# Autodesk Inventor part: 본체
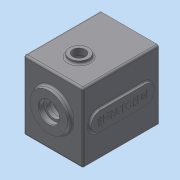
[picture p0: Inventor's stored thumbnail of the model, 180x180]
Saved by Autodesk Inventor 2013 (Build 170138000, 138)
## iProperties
Created: 2016-02
Part Number: 본체
Material: 알루미늄 6061
Document SubType Name: Modeling
Designer: mduedu
Density: 2.71 g/cm^3
Mass: 1515.92 g
Surface Area: 1077.08 cm^2
Volume: 559.38 cm^3
Author: mduedu
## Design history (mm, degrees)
sketch "스케치1"
  geometry: L1 (-47, -47)-(47, -47); L2 (47, -47)-(47, 63); L3 (47, 63)-(-47, 63); L4 (-47, 63)-(-47, -47); 2 further points
  constraints: 8 end point, 2 parallel, 1 horizontal, 1 midpoint, 1 perpendicular, 1 vertical alignment
  dimensions: "d0" = 94 distance of L2.end L3.end; "d155" = 110 distance of L1.end L2.end; "d156" = 47 distance from line of L1 point (0, 0)
extrude "돌출1" new body sketch "스케치1" distance "d2" = 120; taper "d3" = 0 deg
sketch "스케치3"
  geometry: L1 (47, -47)-(-47, -47) reference; L2 (47, 63)-(47, -47) reference; L3 (-47, 63)-(47, 63) reference; L4 (-47, -47)-(-47, 63) reference; L5 (37, 53)-(37, -37); L6 (37, -37)-(-37, -37); L7 (-37, -37)-(-37, 53); L8 (-37, 53)-(37, 53); 1 further point
  constraints: 8 end point, 3 other
  dimensions: "d226" = 10 distance between parallel lines of L8 L3
extrude "돌출3" cut sketch "스케치3" distance "d11" = 110; taper "d12" = 0 deg
sketch "스케치4"
  geometry: C1 r 21 at (0, 11); 1 further point
  constraints: 1 centre point, 1 vertical alignment
  dimensions: "d13" = 21 radius of C1; "d227" = 11 distance of point (0, 0) C1.centre
extrude "돌출4" join sketch "스케치4" distance "d16" = 7; taper "d17" = 0 deg
sketch "스케치5"
  geometry: C1 r 15 at (0, -20); 1 further point
  constraints: 1 centre point, 1 vertical alignment
  dimensions: "d18" = 15 radius of C1; "d20" = 20 distance of point (0, 0) C1.centre
extrude "돌출5" join sketch "스케치5" distance "d21" = 7; taper "d22" = 0 deg
sketch "스케치6"
  geometry: C1 r 30 at (0, 11); A1 r 21 centre (0, 11) between (8.978, -7.984) and (-8.978, -7.984) reference; 1 further point
  constraints: 1 centre point, 1 coincident
  dimensions: "d228" = 60 diameter of C1
extrude "돌출6" join sketch "스케치6" distance "d25" = 7; taper "d26" = -3 deg
hole "구멍1" diameter "d29" = 35; stored, may be unused: countersink angle "d33" = 90 deg, drill point angle "d35" = 0 deg; dims "d27" = 10, "d28" = 10, "d30" = 6, "d31" = 4, "d32" = 2, "d34" = 10
hole "구멍2" diameter "d38" = 22; stored, may be unused: countersink angle "d42" = 90 deg, drill point angle "d44" = 0 deg; dims "d36" = 10, "d37" = 10, "d39" = 6, "d40" = 4, "d41" = 2, "d43" = 7
hole "구멍3" diameter "d47" = 19; stored, may be unused: countersink angle "d51" = 90 deg, drill point angle "d53" = 0 deg; dims "d45" = 10, "d46" = 10, "d48" = 6, "d49" = 4, "d50" = 2, "d52" = 1
hole "구멍4" diameter "d56" = 32; stored, may be unused: countersink angle "d60" = 90 deg, drill point angle "d62" = 0 deg; dims "d57" = 6, "d58" = 4, "d59" = 2, "d61" = 8, "d220" = 10, "d221" = 10
hole "구멍5" diameter "d65" = 25; stored, may be unused: countersink angle "d69" = 90 deg, drill point angle "d71" = 0 deg; dims "d63" = 10, "d64" = 10, "d66" = 6, "d67" = 4, "d68" = 2, "d70" = 8
fillet "모깎기2" dims "d73" = 0.3
fillet "모깎기3" dims "d74" = 2
chamfer "모따기1" distance "d75" = 1; stored, may be unused: second distance "d76" = 2, angle "d77" = 45 deg
fillet "모깎기4" dims "d78" = 3
fillet "모깎기23" dims "d240" = 1
fillet "모깎기20" dims "d229" = 3
sketch "스케치23"
  geometry: L1 (-37, 53)-(37, 53) reference; L2 (37, 53)-(37, -37) reference; L3 (37, -37)-(-37, -37) reference; L4 (-37, -37)-(-37, 53) reference; L5 (44, -47)-(-44, -47) reference; L6 (47, 60)-(47, -44) reference; L7 (-44, 63)-(44, 63) reference; L8 (-47, -44)-(-47, 60) reference; C1 r 10 at (-37, 53); C2 r 10 at (37, 53); C3 r 10 at (-37, -37); C4 r 10 at (37, -37); A1 r 3 centre (-44, -44) between (-47, -44) and (-44, -47) reference; A2 r 3 centre (44, -44) between (44, -47) and (47, -44) reference; A3 r 3 centre (44, 60) between (47, 60) and (44, 63) reference; A4 r 3 centre (-44, 60) between (-44, 63) and (-47, 60) reference; 1 further point
  constraints: 4 centre point, 4 coincident, 3 equal radius
  dimensions: "d230" = 20 diameter of C1
extrude "돌출22" join sketch "스케치23" stored distance "d235" = 10; taper "d236" = 0 deg
fillet "모깎기21" dims "d237" = 3
node "작업 평면1"
fillet "모깎기22" dims "d239" = 1
sketch "스케치12"
  geometry: A1 r 10 centre (-37, 53) between (-34.692, 43.27) and (-27.27, 50.692) reference; A2 r 10 centre (37, 53) between (27.27, 50.692) and (34.692, 43.27) reference; A3 r 10 centre (37, -37) between (34.692, -27.27) and (27.27, -34.692) reference; A4 r 10 centre (-37, -37) between (-27.27, -34.692) and (-34.692, -27.27) reference; 5 further points
  constraints: 4 coincident
hole "구멍6" sketch "스케치12" at (-37, 53), (37, 53), (37, -37), (-37, -37) diameter "d122" = 3.242; stored, may be unused: countersink angle "d126" = 90 deg, drill point angle "d128" = 120 deg; dims "d123" = 7, "d124" = 4, "d125" = 2, "d127" = 9
sketch "스케치20"
  geometry: L1 (44, 0)-(-44, 0) reference; L2 (44, -120)-(-44, -120) reference; L3 (0, 0)-(0, -120); L4 (-44, -120)-(-44, 0) reference; L5 (44, 0)-(44, -120) reference; C1 r 10 at (0, -79)
  constraints: 2 end point, 1 centre point, 1 midpoint, 1 point on line
  dimensions: "d189" = 20 diameter of C1; "d190" = 41 distance from line of C1.centre L2
extrude "돌출19" cut sketch "스케치20" stored distance "d191" = 10; taper "d192" = 0 deg
sketch "스케치18"
  geometry: C1 r 15 at (0, -79); C2 r 10 at (0, -79) reference; 1 further point
  constraints: 1 centre point, 1 concentric
  dimensions: "d174" = 30 diameter of C1
extrude "돌출17" join sketch "스케치18" distance "d175" = 5; taper "d176" = 0 deg
fillet "모깎기16" dims "d177" = 3
sketch "스케치19"
  geometry: C1 r 15 at (24.351, 79); C2 r 10 at (24.351, 79) reference; 1 further point
  constraints: 1 centre point, 1 concentric
  dimensions: "d178" = 30 diameter of C1
extrude "돌출18" cut sketch "스케치19" distance "d181" = 5; taper "d182" = 0 deg
chamfer "모따기5" distance "d183" = 1; stored, may be unused: second distance "d184" = 2, angle "d185" = 45 deg
fillet "모깎기24" dims "d242" = 3, "d243" = 3
sketch "스케치24"
  geometry: L1 (-95, 67)-(-25, 67); L2 (-25, 67)-(-25, 37); L3 (-25, 37)-(-95, 37); L4 (-95, 37)-(-95, 67); L5 (0, 0)-(0, 104) reference; L6 (-95, 52)-(-25, 52); L7 (-60, 67)-(-60, 37); A1 r 15 centre (-95, 52) between (-95, 37) and (-95, 67); A2 r 15 centre (-25, 52) between (-25, 67) and (-25, 37); A3 r 15 centre (-25, 52) between (-25, 37) and (-25, 67); A4 r 15 centre (-95, 52) between (-95, 67) and (-95, 37); 2 further points
  constraints: 12 end point, 8 point on circle, 5 midpoint, 4 centre point, 2 parallel, 2 perpendicular, 1 horizontal, 1 horizontal alignment
  dimensions: "d244" = 60 distance between parallel lines of L7 L5; "d245" = 100 dimension on A2 A1; "d246" = 30 distance between parallel lines of L3 L1
extrude "돌출23" join sketch "스케치24" distance "d247" = 3; taper "d248" = 0 deg
fillet "모깎기25" dims "d249" = 3
sketch "스케치25"
  geometry: L1 (-25, 67)-(-95, 67) reference; L2 (-95, 37)-(-25, 37) reference; A1 r 15 centre (-95, 52) between (-95, 67) and (-95, 37) reference; A2 r 15 centre (-25, 52) between (-25, 37) and (-25, 67) reference; 3 further points
  constraints: 1 horizontal alignment, 1 midpoint, 1 vertical alignment, 1 other
feature "엠보싱3" sketch "스케치25" dims "d250" = 0.5, "d251" = 0
sketch "스케치26"
  geometry: L1 (14.367, 127)-(73.633, 127) reference; L2 (0, 0)-(88, 0) reference; L3 (88, 120)-(0, 120) reference; 5 further points
  constraints: 3 vertical alignment, 2 midpoint
  dimensions: "d252" = 35 distance from line of point (44, 35) L2; "d253" = 35 distance from line of point (44, 85) L3; "d254" = 50 distance of point (44, 35) point (44, 85) (derived)
hole "구멍8" sketch "스케치26" at (44, 85), (44, 35) diameter "d255" = 6.647; stored, may be unused: countersink angle "d259" = 90 deg, drill point angle "d261" = 118 deg; dims "d256" = 6, "d257" = 4, "d258" = 2, "d260" = 8
node "솔리드1"
node "투영된 루프1"
node "투영된 루프4"
node "투영된 루프5"
node "투영된 루프6"
